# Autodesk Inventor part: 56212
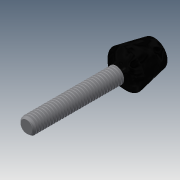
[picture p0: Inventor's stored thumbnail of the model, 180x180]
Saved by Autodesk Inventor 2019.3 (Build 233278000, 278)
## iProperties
Created: 2012-09
Part Number: 56212
Material: Ogólny
Document SubType Name: Modeling
Designer: CADENGINEERING4
Density: 1 g/cm^3
Appearance: Domyślna
Author: CADENGINEERING4
Revision Number: ÈÎºÎ
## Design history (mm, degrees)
feature "Ðý×ª2"
node "Bryła1"
